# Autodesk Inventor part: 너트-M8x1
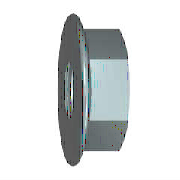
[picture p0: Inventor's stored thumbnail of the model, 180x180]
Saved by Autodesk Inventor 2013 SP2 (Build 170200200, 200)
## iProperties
Created: 2015-12
Part Number: 너트-M8x1
Material: 스테인리스강
Description: 플랜지붙이 6각 너트 - 일반 스레드
Document SubType Name: Modeling
Standard: ISO 4161
Designer: mdu
Standard Revision: 2판 1999-03-15
Standards Organization: ISO
Language: ko-KR
Size Designation: M8
Categories: <MemberInstance><Categories><Category DisplayName="조임쇠" InternalName="e4da775c-781d-43d5-af7c-5136215cf5a6" Mnemonic="FSTN"><Category DisplayName="너트" InternalN
Density: 8.08 g/cm^3
Author: mdu
IsCustomPart: 1
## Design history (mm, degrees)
sketch "스케치1"
  geometry: L1 (-1.844, 0)-(9.641, 0) reference; L2 (3.107, 6.5)-(2.288, 8.257); L3 (3.107, 6.5)-(8, 6.5); L4 (8, 6.5)-(8, 0); L5 (3.107, 6.5)-(3.107, 0); L6 (0, -1.835)-(0, 11.01) reference; A1 r 1.2 centre (1.2, 7.75) between (2.288, 8.257) and (0, 7.75); 1 further point
  constraints: 8 end point, 3 point on line, 2 perpendicular, 2 point on circle, 2 tangent, 1 centre point, 1 parallel
  dimensions: "d2" = 13 diameter of L3 L1 (= SW); "d4" = 17.9 dimension on A1 L1 (= LADI); "d5" = 1.2 radius of A1 (= PHH); "d15" = 8 distance between parallel lines of L4 L6 (= KOH); "d16" = 25 deg angle of L6 L2 (= KEWI)
revolve "링" sketch "스케치1" stored, may be unused: angle "d8" = 90 deg
sketch "스케치2"
  geometry: L1 (-6.5, -3.753)-(-6.5, 3.753); L2 (-6.5, 3.753)-(0, 7.506); L3 (0, 7.506)-(6.5, 3.753); L4 (6.5, 3.753)-(6.5, -3.753); L5 (6.5, -3.753)-(0, -7.506); L6 (0, -7.506)-(-6.5, -3.753); C1 r 4.9 at (0, 0); C2 r 7.75 at (0, 0) reference; 1 further point
  constraints: 12 end point, 1 centre point, 1 coincident, 1 vertical, 11 other
  dimensions: "d6" = 15.01111 distance of L5.end L2.end (= 1.1547 x SW)
extrude "본체" join sketch "스케치2" distance "d7" = 8 (= KOH); taper "d9" = 0 deg
sketch "스케치3"
  geometry: L1 (2.638, 7.506)-(8, 7.506) reference; L2 (8, 3.753)-(8, 7.506) reference; L3 (0, -7.75)-(0, 7.75) reference; L4 (-1.6, 0)-(9.6, 0) reference; L5 (7.419, 7.506)-(8, 6.5)
  constraints: 2 end point, 2 point on line
  dimensions: "d10" = 30 deg angle of L2 L5 (= ANG1); "d11" = 13 diameter of L5.end L4 (= SW0)
revolve "모따기1" sketch "스케치3" stored, may be unused: angle "d24" = 90 deg
sketch "스케치4"
  geometry: C1 r 7.75 at (0, 0) reference; 1 further point
  constraints: 1 coincident
hole "스레드" sketch "스케치4" at (0, 0) diameter "d25" = 6.647; stored, may be unused: countersink angle "d29" = 82 deg, drill point angle "d31" = 118 deg; dims "d26" = 6, "d27" = 4, "d28" = 2, "d30" = 8
workaxis "Work Axis1"
workplane "Work Plane1"
body "Solid1"
chamfer "모따기2" distance "d12" = 0.67658 (= -0.5 x GD1 + 0.5 x NND); stored, may be unused: angle "d13" = 30 deg, second distance "d46" = 0.67658 (= -0.5 x GD1 + 0.5 x NND)
chamfer "모따기3" distance "d51" = 0.67658 (= -0.5 x GD1 + 0.5 x NND); stored, may be unused: second distance "d52" = 2, angle "d53" = 45 deg
other parameters: "ANG1" = 30 deg [user parameter; used in 1 equation term], "KEWI" = 25 deg [user parameter; used in 1 equation term], "NND" = 8 [user parameter; used in 4 equation terms], "LADI" = 17.9 [user parameter; used in 2 equation terms], "SW" = 13 [user parameter; used in 3 equation terms], "PHH" = 1.2 [user parameter; used in 3 equation terms], "KOH" = 8 (= NND) [user parameter; used in 2 equation terms], "SW0" = 13 [user parameter; used in 1 equation term], "GD1" = 6.64684 (computed from THREADDIA, PTC, TOA) [user parameter; used in 3 equation terms], "d1" = 17.9 (= LADI), "d3" = 1.2 (= PHH), "d45" = 0, "d47" = 0, "d49" = 0, "d54" = 0, "GUL" = 0.67658 (= 0.541266 x PTC) [user parameter], "TPU" = 8 (computed from PTC) [user parameter], "RR" = 1.2 (= PHH) [user parameter], "THREADDIA" = 8 [user parameter; used in 1 equation term], "TOA" = 30 deg [user parameter; used in 1 equation term], "PTC" = 1.25 [user parameter; used in 4 equation terms], "GAL" = 0.67658 (= 0.541266 x PTC) [user parameter], "E0" = 15.015 (= 1.155 x SW) [user parameter]
